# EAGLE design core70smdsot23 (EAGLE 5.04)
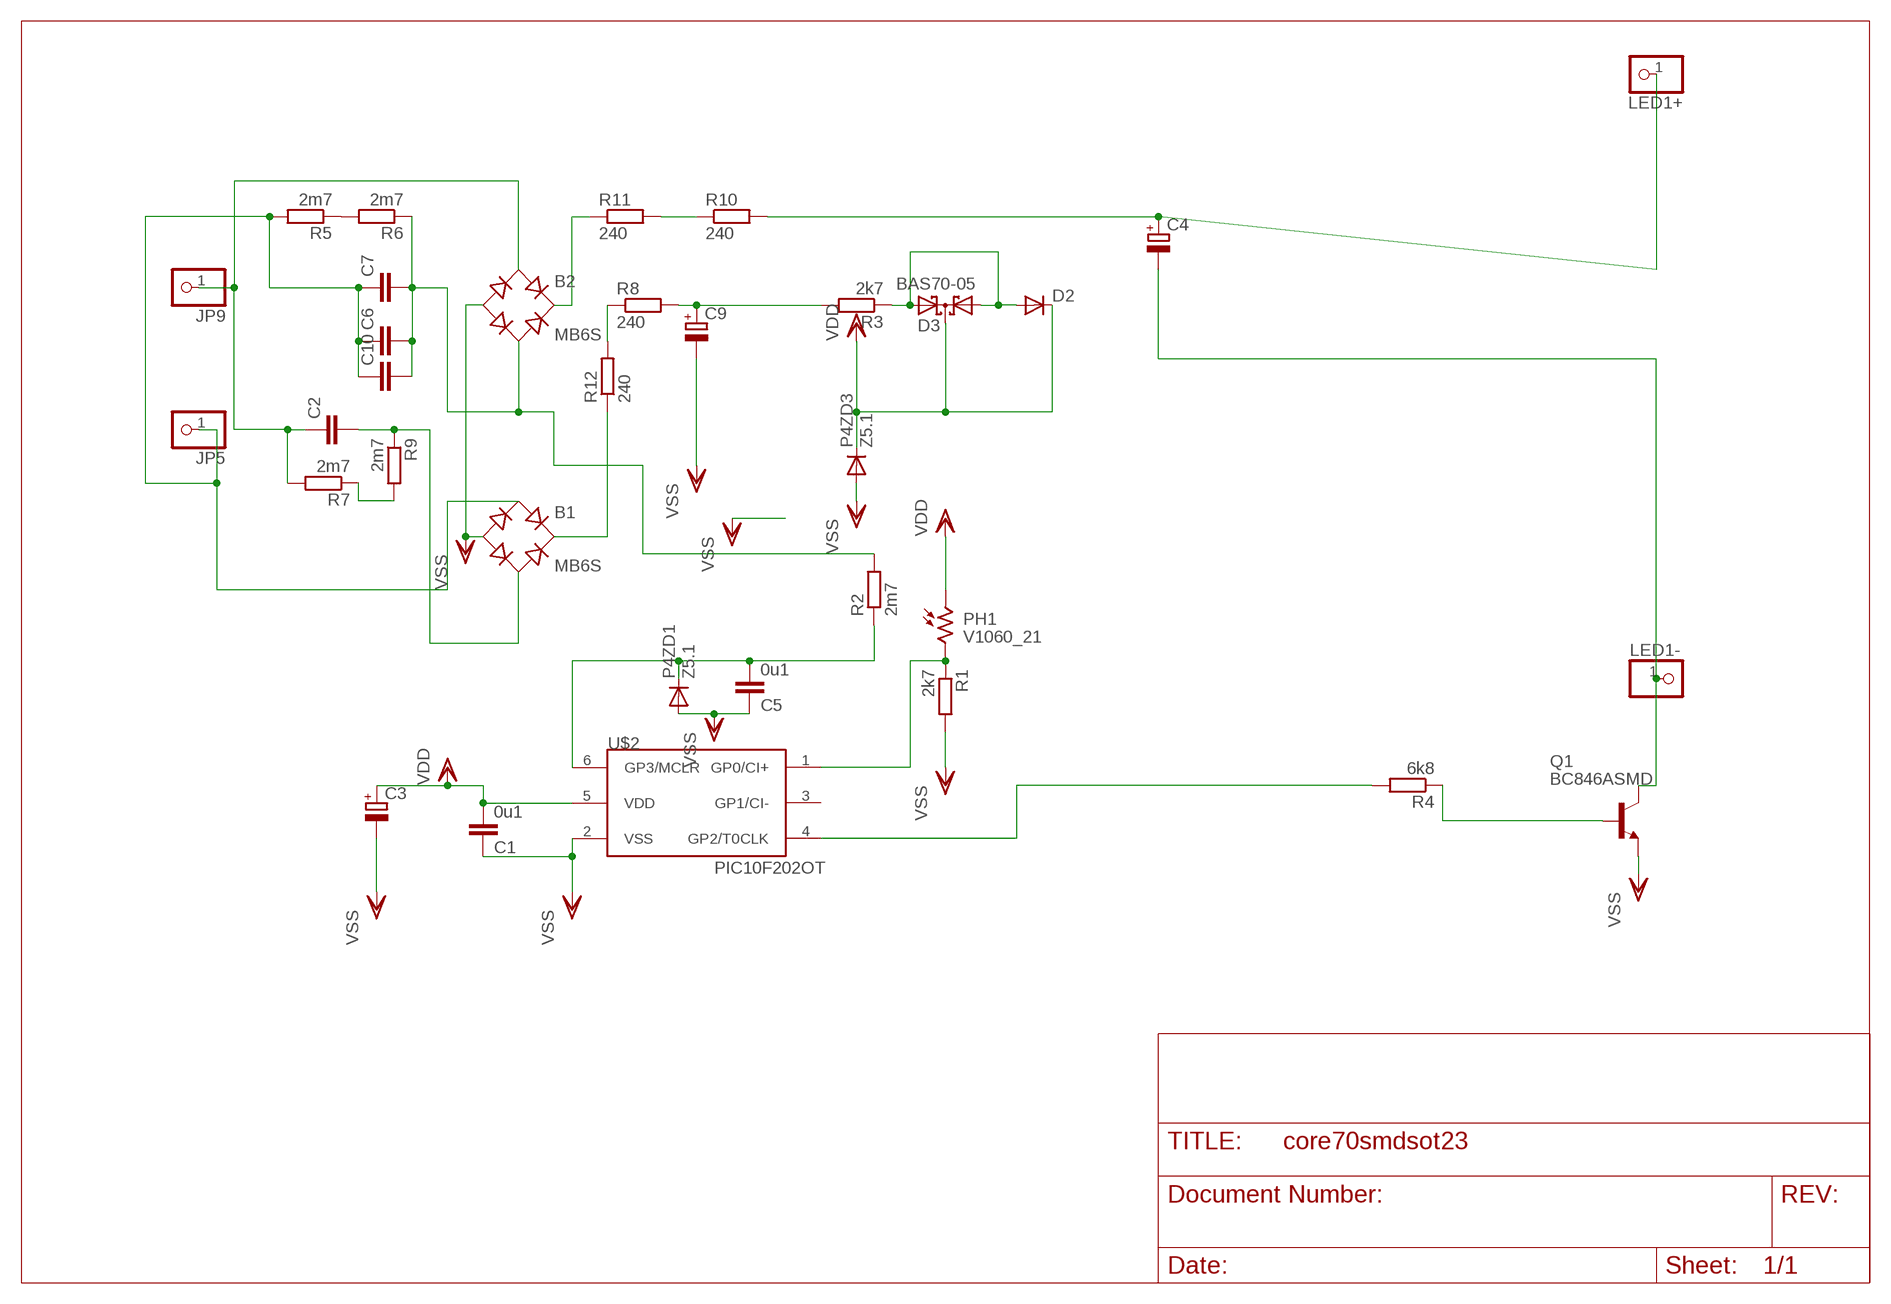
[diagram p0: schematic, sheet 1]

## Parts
B1  MB6S  [SOIC-4]
B2  MB6S  [SOIC-4]
C1  0u1  C-EUC1206  [C1206]
C2  C-EUC4564  [C4564]
C3  CPOL-EUB  [PANASONIC_B]
C4  CPOL-EUSMCE  [SMC_E]
C5  0u1  C-EUC1206  [C1206]
C6  C-EUC4564  [C4564]
C7  C-EUC4564  [C4564]
C9  CPOL-EUSMCD  [SMC_D]
C10  C-EUC4564  [C4564]
D2  DIODE-MINIMELF  [MINIMELF]
D3  BAS70-05  [SOT23]
JP5  PINHD-1X1  [1X01]
JP9  PINHD-1X1  [1X01]
LED1+  PINHD-1X1  [1X01]
LED1-  PINHD-1X1  [1X01]
P4ZD1  Z5.1  DIODE-MINIMELF  [MINIMELF]
P4ZD3  Z5.1  DIODE-MINIMELF  [MINIMELF]
PH1  V1060_21  [TO-5_V10]
Q1  BC846ASMD  [SOT23]
R1  2k7  R-EU_R0805  [R0805]
R2  2m7  R-EU_R1206  [R1206]
R3  2k7  R-EU_R1206  [R1206]
R4  6k8  R-EU_R1206  [R1206]
R5  2m7  R-EU_R1210  [R1210]
R6  2m7  R-EU_R1210  [R1210]
R7  2m7  R-EU_R1210  [R1210]
R8  240  R-EU_R1210  [R1210]
R9  2m7  R-EU_R1210  [R1210]
R10  240  R-EU_R2010  [R2010]
R11  240  R-EU_R2010  [R2010]
R12  240  R-EU_R1210  [R1210]
U$2  PIC10F202OT  [SOT23-6]

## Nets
AC1: B1.~1(AC1) C6.1 C7.1 C10.1 JP5.1 R5.2
AC2: B2.~1(AC1) C2.1 JP9.1 R7.2
CBIG: B2.~2(AC2) C6.2 C7.2 C10.2 R2.2 R6.1
D+: C4.+ LED1+.1 R10.2
D-: C4.- LED1-.1 Q1.3(C)
DR+: C9.+ R3.2 R8.2
N$1: C5.2 P4ZD1.C R2.1 U$2.6(GP3/MCLR)
N$2: R5.1 R6.2
N$3: R7.1 R9.2
N$4: R8.1 R12.2
N$5: D2.A D3.1(A1) D3.2(A2) R3.1
N$6: R10.1 R11.2
N$8: B1.~2(AC2) C2.2 R9.1
N$11: B2.+ R11.1
N$12: Q1.1(B) R4.1
N$15: R4.2 U$2.4(GP2/T0CLK)
N$17: PH1.2 R1.1 U$2.1(GP0/CI+)
RECDR+: B1.+ R12.1
VDD: C1.2 C3.+ D2.C D3.3(C) P4ZD3.C PH1.1 U$2.5(VDD)
VSS: B1.- B2.- C1.1 C3.- C5.1 C9.- P4ZD1.A P4ZD3.A Q1.2(E) R1.2 U$2.2(VSS)
Unconnected: U$2.3(GP1/CI-)

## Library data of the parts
B1 B2 = rectifier:MB*S: Bridge Rectifier Source: http://www.fairchildsemi.com/ds/MB/MB6S.pdf
C1 C5 = rcl:C-EU: CAPACITOR, European symbol
C2 C6 C7 C10 = rcl-2:C-EU: CAPACITOR, European symbol
C3 C4 C9 = rcl-2:CPOL-EU: POLARIZED CAPACITOR, European symbol
D2 P4ZD1 P4ZD3 = diode:DIODE-: DIODE
D3 = diode:BAS70-05: Silicon Schottky Diodes General-purpose diode for high-speed switching
JP5 JP9 LED1+ LED1- = pinhead(2):PINHD-1X1: PIN HEADER
PH1 = photo-elements:?1060*: Sensor Street Light control
Q1 = transistor-npn:BC846*: NPN Transistor
R1-R12 = rcl-2:R-EU_: RESISTOR, European symbol
U$2 = microchip-3:PIC10F2*: uPC nW 0,25/0,5k Program Flash memory Comparator

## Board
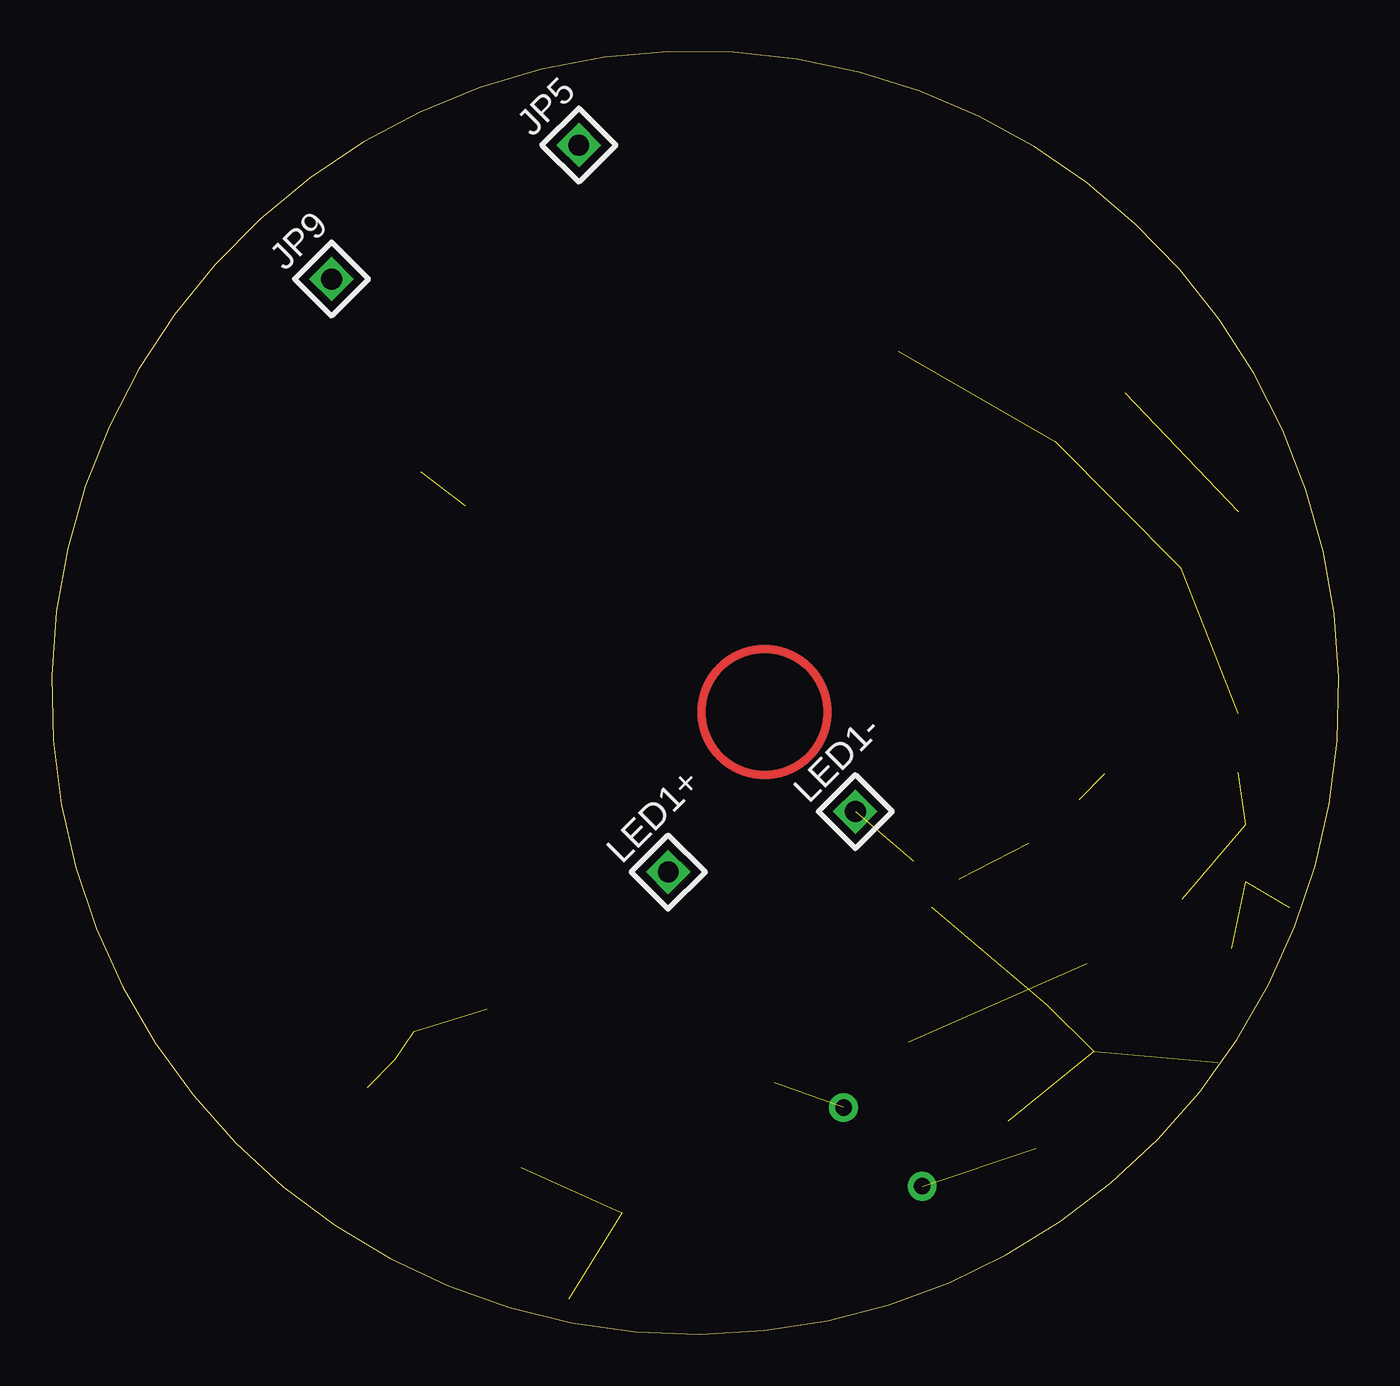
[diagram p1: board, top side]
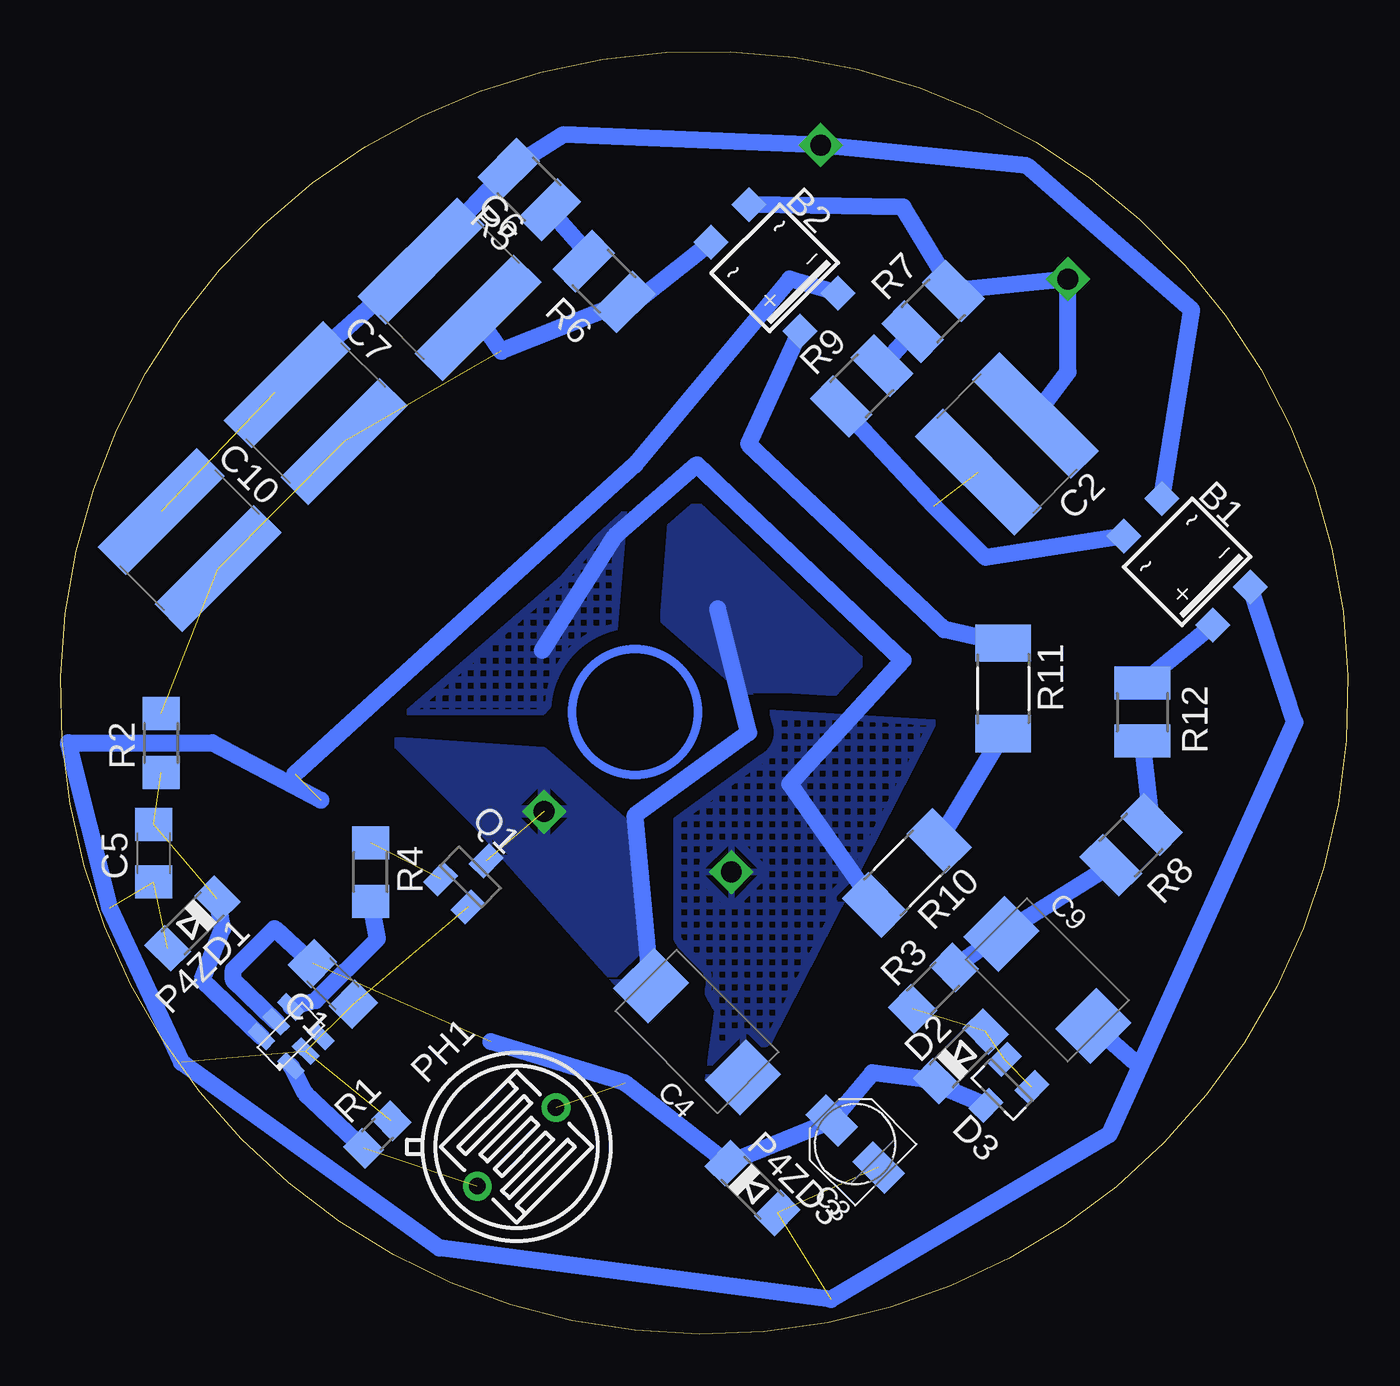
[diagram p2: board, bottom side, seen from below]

Size 62.45 x 62.23 mm. Coordinates in mm from the lower left corner, seen from the top.
Outline: 34.58,0.19 arc171 33.08,62.19 arc190 34.58,0.19
Copper layers (1*16): Top 0.035mm / dielectric 1.5mm / Bottom 0.035mm
Design rules "default": minimum track width 10mil, minimum drill 24mil, track to track 8mil, track to pad 8mil, pad to pad 8mil, via to via 8mil, smd to smd 8mil, copper to edge 40mil, drill to drill 8mil, minimum pad ring 10mil, minimum via ring 8mil, stop-mask expansion 4mil, vias tented up to drill 0mil, thermal gap 10mil

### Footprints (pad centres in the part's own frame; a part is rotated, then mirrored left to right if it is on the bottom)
SOIC-4 = smd 1.2 x 1.2: + 1.3,3.05; - -1.3,3.05; ~1 -1.3,-3.05; ~2 1.3,-3.05
C1206 = smd 1.6 x 1.8: 1 -1.4,0; 2 1.4,0
C4564 = smd 1.9 x 6.8: 1 -1.95,0; 2 1.95,0
PANASONIC_B = smd 2.2 x 1.4: + 1.6,0; - -1.6,0
SMC_E = smd 2.4 x 2.8: + -3.15,0; - 3.15,0
SMC_D = smd 2.4 x 2.8: + -3.15,0; - 3.15,0
MINIMELF = smd 1.4 x 1.8: A 1.7,0; C -1.7,0
SOT23 = smd 1 x 1.4: 1 -0.95,-1.1; 2 0.95,-1.1; 3 0,1.1
1X01 = drill 1.016 square: 1 0,0
TO-5_V10 = drill 0.8 pad 1.4 round: 1 -2.7,0; 2 2.7,0
R0805 = smd 1.3 x 1.5: 1 -0.95,0; 2 0.95,0
R1206 = smd 1.6 x 1.803: 1 -1.422,0; 2 1.422,0
R1210 = smd 1.6 x 2.7: 1 -1.4,0; 2 1.4,0
R2010 = smd 1.8 x 2.7: 1 -2.2,0; 2 2.2,0
SOT23-6 = smd 0.635 x 1.27: 1 -1.016,-1.016; 2 0,-1.016; 3 1.016,-1.016; 4 1.016,1.016; 5 0,1.016; 6 -1.016,1.016

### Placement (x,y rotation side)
B1  7.8,37.48 225 bottom
B2  27.81,51.74 225 bottom
C1  49.24,17 135 bottom
C2  16.54,43.2 225 bottom
C3  23.9,9.23 135 bottom
C4  31.58,14.69 135 bottom
C5  57.93,23.34 90 bottom
C6  43.58,50.69 315 bottom
C7  50.08,44.69 315 bottom
C9  14.58,17.19 315 bottom
C10  56.19,38.54 315 bottom
D2  18.78,13.49 45 bottom
D3  16.78,11.88 135 bottom
JP5  25.58,57.69 45 top
JP9  13.58,51.19 45 top
LED1+  29.92,22.43 45 top
LED1-  38.99,25.36 45 top
P4ZD1  56.05,19.93 225 bottom
P4ZD3  28.88,7.1 315 bottom
PH1  40.33,9.09 225 bottom
Q1  42.58,22.19 315 bottom
R1  47.08,9.69 45 bottom
R2  57.58,28.69 90 bottom
R3  20.12,16.79 45 bottom
R4  47.42,22.42 270 bottom
R5  39.73,55.54 135 bottom
R6  36.08,51.07 135 bottom
R7  20.13,49.63 45 bottom
R8  10.52,23.75 225 bottom
R9  23.6,46 45 bottom
R10  21.4,22.39 225 bottom
R11  16.73,31.34 270 bottom
R12  9.98,30.19 270 bottom
U$2  51.28,14.45 45 bottom

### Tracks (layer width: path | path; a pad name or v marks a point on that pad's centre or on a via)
AC1  (1 unrouted)
  Bottom 0.813: B1.~1 7.58,49.69 15.58,56.69 JP5.1 38.08,58.19 R5.2 C6.1 52.08,45.69 C7.1
AC2
  Bottom 0.813: B2.~1 21.58,54.69 R7.2 JP9.1 13.58,46.69 C2.1
CBIG  (3 unrouted)
  Bottom 0.813: B2.~2 35.08,49.69 R6.1 41.08,47.69 C6.2
D+
  Bottom 0.813: R10.2 27.08,26.69 21.58,32.69 31.58,42.19 35.58,38.69 39.08,33.19
  pour Bottom (isolate 0.813, hatched): 38.08,36.69 45.58,30.19 39.08,30.19 35.58,34.19 35.08,40.19
  pour Bottom (isolate 0.813, hatched): 28.08,14.19 20.08,29.69 28.58,30.19 32.58,26.69 32.58,19.19 30.58,15.69 31.08,12.19
D-  (1 unrouted)
  Bottom 0.813: C4.- 34.58,25.19 29.08,29.19 30.58,35.19
  pour Bottom (isolate 0.813, rank 2): 42.08,24.69 34.08,15.69 35.08,24.69 39.08,28.19 46.08,28.69
  pour Bottom (isolate 0.813, rank 2): 24.08,33.69 32.58,41.19 33.08,34.69 29.08,31.19 23.08,30.69
DR+
  Bottom 0.813: R8.2 C9.+ R3.2
N$1  (2 unrouted)
  Bottom 0.813: U$2.6 55.58,17.19 54.58,19.69 P4ZD1.C
N$2
  Bottom 0.813: R5.1 37.08,52.69 R6.2
N$3
  Bottom 0.813: R7.1 R9.2
N$4
  Bottom 0.813: R8.1 R12.2
N$5  (3 unrouted)
N$6
  Bottom 0.813: R10.1 R11.2
N$8  (1 unrouted)
  Bottom 0.813: B1.~2 17.58,37.69 20.08,40.19 R9.1
N$11
  Bottom 0.813: B2.+ 29.08,43.19 19.58,34.19 R11.1
N$12  (1 unrouted)
N$15
  Bottom 0.813: U$2.4 50.08,16.19 47.08,19.19 R4.2
N$17  (1 unrouted)
  Bottom 0.813: R1.1 50.58,11.69 U$2.1
RECDR+
  Bottom 0.813: B1.+ R12.1
VDD  (2 unrouted)
  Bottom 0.813: 20.56,12.36 D2.C | 20.56,12.36 23.08,12.69 C3.+ P4ZD3.C 35.08,12.19 41.58,14.19 | C1.2 52.08,19.69 54.08,17.69 54.08,17.19 U$2.5 | D3.3 20.56,12.36
VSS  (9 unrouted)
  Bottom 0.813: B2.- 27.08,51.19 34.58,42.19 51.08,27.19 | B1.- 2.58,29.69 10.1,12.98 | 10.1,12.98 11.58,9.69 25.08,1.69 44.08,4.19 56.58,13.19 60.08,20.69 62.08,28.69 55.08,28.69 49.83,25.92 | 10.1,12.98 C9.-
(copper drawn outside any net)
  shapes: Bottom circle x1, Top circle x1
